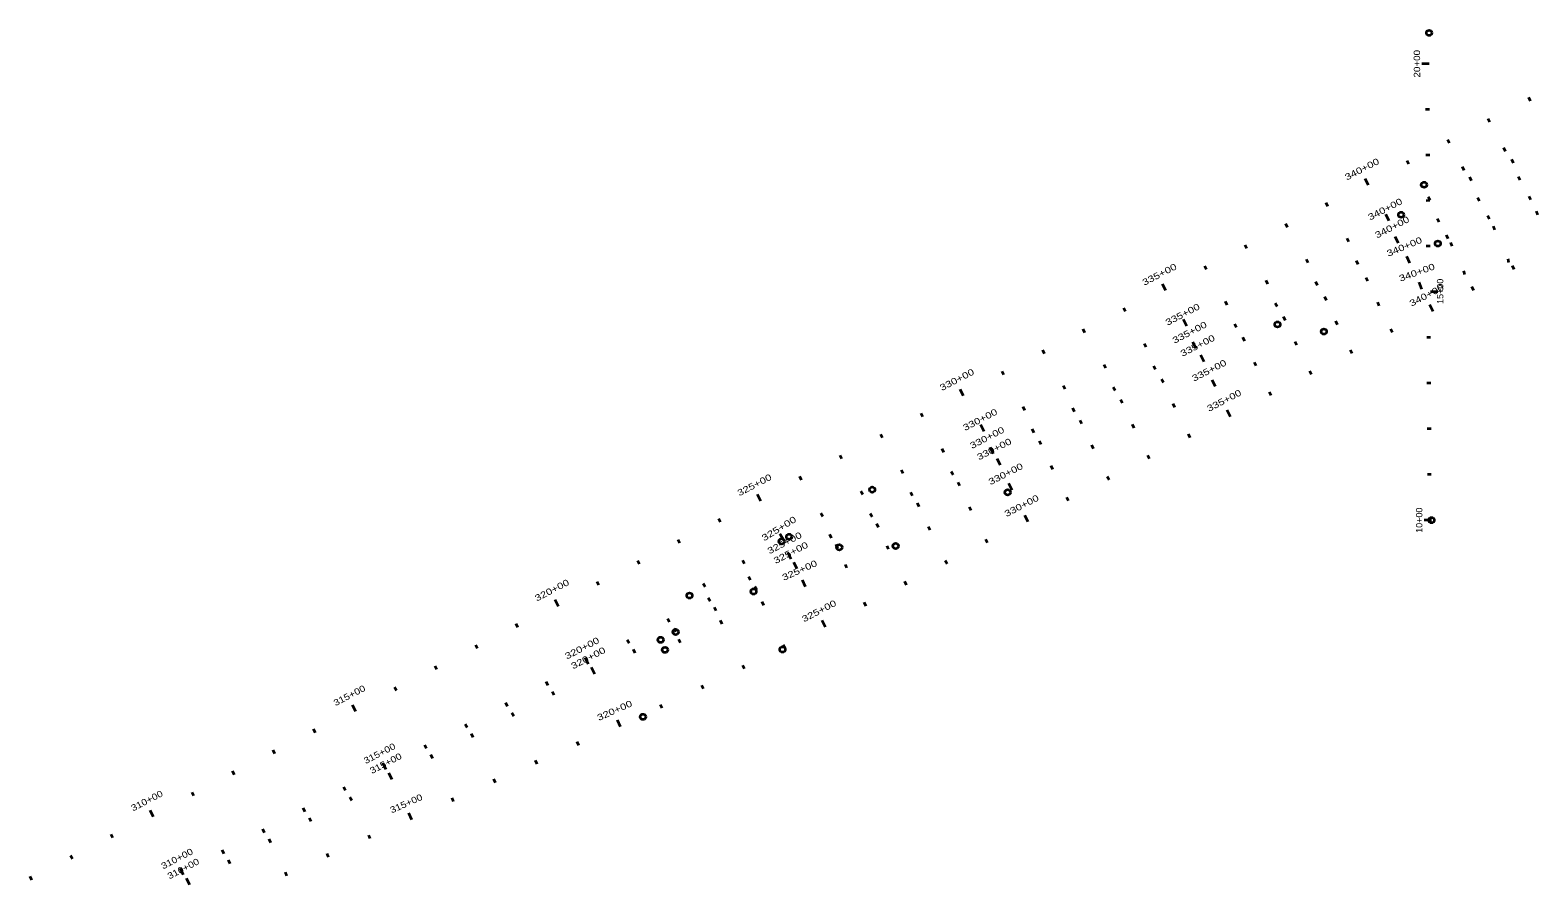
# Model space of a CAD drawing. Extents: x 2357892 to 2370172, y 6966790 to 6985499.
# Drawn here: x 2358624 to 2361928, y 6976232 to 6978104 of the extents above; entities that cross this region are included whole.
import ezdxf
from ezdxf.enums import TextEntityAlignment as Align

# ---------------------------------------------------------------- set-up
doc = ezdxf.new("R2010")
doc.units = 0
doc.header["$LTSCALE"] = 5.6
doc.layers.add('28', color=7, linetype='Continuous', lineweight=35)

msp = doc.modelspace()

# ---------------------------------------------------------------- linework, layer by layer
at = {"layer": '28'}
for p, q in [((2361689.654, 6978030.649), (2361673.654, 6978030.571)), ((2361911.419, 6977948.732), (2361907.499, 6977956.274)), ((2361690.143, 6977930.65), (2361681.643, 6977930.609)), ((2361822.689, 6977902.614), (2361818.769, 6977910.156)), ((2361733.958, 6977856.495), (2361730.038, 6977864.037)), ((2361645.228, 6977810.376), (2361641.308, 6977817.919)), ((2361690.632, 6977830.651), (2361682.132, 6977830.61)), ((2361852.631, 6977846.747), (2361856.096, 6977838.985)), ((2361873.898, 6977813.13), (2361870.708, 6977821.009)), ((2361761.677, 6977805.189), (2361765.276, 6977797.489)), ((2361888.729, 6977775.541), (2361884.809, 6977783.083)), ((2361556.498, 6977764.258), (2361549.119, 6977778.455)), ((2361781.88, 6977773.993), (2361778.418, 6977781.755)), ((2361467.767, 6977718.139), (2361463.847, 6977725.681)), ((2361691.121, 6977730.653), (2361682.622, 6977730.611)), ((2361691.285, 6977731.668), (2361687.553, 6977739.305)), ((2361799.996, 6977729.427), (2361796.076, 6977736.969)), ((2361912.073, 6977732.338), (2361908.457, 6977740.031)), ((2361602.153, 6977686.337), (2361594.775, 6977700.534)), ((2361711.263, 6977683.312), (2361707.344, 6977690.854)), ((2361821.568, 6977689.806), (2361817.953, 6977697.499)), ((2361927.536, 6977699.692), (2361924.809, 6977707.743)), ((2361379.037, 6977672.021), (2361375.117, 6977679.563)), ((2361622.531, 6977637.198), (2361615.153, 6977651.395)), ((2361731.064, 6977647.274), (2361727.449, 6977654.967)), ((2361833.201, 6977666.517), (2361830.288, 6977674.502)), ((2361290.306, 6977625.902), (2361286.386, 6977633.444)), ((2361513.421, 6977640.222), (2361509.501, 6977647.765)), ((2361691.61, 6977630.654), (2361683.111, 6977630.612)), ((2361739.664, 6977631.157), (2361736.566, 6977639.072)), ((2361201.576, 6977579.784), (2361197.656, 6977587.326)), ((2361424.688, 6977594.108), (2361420.768, 6977601.65)), ((2361533.798, 6977591.084), (2361529.879, 6977598.626)), ((2361646.974, 6977593.631), (2361640.798, 6977608.391)), ((2361864.288, 6977595.163), (2361862.239, 6977603.412)), ((2361875.682, 6977580.078), (2361871.763, 6977587.621)), ((2361335.955, 6977547.994), (2361332.036, 6977555.536)), ((2361445.066, 6977544.969), (2361441.146, 6977552.512)), ((2361555.182, 6977553.96), (2361551.72, 6977561.723)), ((2361673.062, 6977536.888), (2361667.603, 6977551.928)), ((2361767.912, 6977568.529), (2361765.434, 6977576.66)), ((2361112.846, 6977533.665), (2361105.467, 6977547.862)), ((2361464.338, 6977512.166), (2361460.695, 6977519.846)), ((2361708.1, 6977530.733), (2361692.1, 6977530.655)), ((2361786.942, 6977533.979), (2361783.023, 6977541.522)), ((2361024.115, 6977487.546), (2361020.195, 6977495.089)), ((2361247.223, 6977501.88), (2361243.303, 6977509.422)), ((2361356.333, 6977498.855), (2361352.413, 6977506.397)), ((2361579.998, 6977500.326), (2361576.684, 6977508.153)), ((2361698.201, 6977487.879), (2361690.825, 6977502.078)), ((2361158.49, 6977455.765), (2361151.112, 6977469.963)), ((2361267.6, 6977452.741), (2361263.681, 6977460.283)), ((2361374.489, 6977468.27), (2361370.67, 6977475.864)), ((2361488.975, 6977458.943), (2361485.255, 6977466.587)), ((2360935.385, 6977441.428), (2360931.465, 6977448.97)), ((2361178.868, 6977406.627), (2361171.49, 6977420.824)), ((2361285.339, 6977422.969), (2361281.485, 6977430.545)), ((2361399.709, 6977413.873), (2361395.855, 6977421.45)), ((2361609.461, 6977441.78), (2361605.543, 6977449.323)), ((2361692.589, 6977430.656), (2361684.089, 6977430.615)), ((2360846.655, 6977395.309), (2360842.735, 6977402.851)), ((2361069.758, 6977409.651), (2361065.838, 6977417.193)), ((2361196.209, 6977377.628), (2361188.954, 6977391.889)), ((2361520.721, 6977395.68), (2361516.802, 6977403.223)), ((2360757.924, 6977349.191), (2360754.004, 6977356.733)), ((2360981.025, 6977363.537), (2360977.105, 6977371.079)), ((2361090.135, 6977360.512), (2361086.216, 6977368.055)), ((2361310.576, 6977368.538), (2361306.722, 6977376.114)), ((2361431.98, 6977349.581), (2361428.062, 6977357.124)), ((2360892.292, 6977317.423), (2360888.373, 6977324.965)), ((2361001.403, 6977314.398), (2360997.483, 6977321.94)), ((2361107.078, 6977332.287), (2361103.224, 6977339.863)), ((2361221.443, 6977323.202), (2361214.189, 6977337.463)), ((2361693.078, 6977330.657), (2361684.578, 6977330.616)), ((2360669.194, 6977303.072), (2360661.815, 6977317.269)), ((2361017.948, 6977286.947), (2361014.094, 6977294.523)), ((2361343.24, 6977303.481), (2361339.322, 6977311.024)), ((2360580.464, 6977256.954), (2360576.543, 6977264.496)), ((2360803.56, 6977271.308), (2360799.64, 6977278.851)), ((2360912.67, 6977268.284), (2360908.75, 6977275.826)), ((2361132.31, 6977277.866), (2361128.456, 6977285.442)), ((2361254.5, 6977257.382), (2361247.124, 6977271.58)), ((2360714.827, 6977225.194), (2360707.449, 6977239.391)), ((2360823.938, 6977222.169), (2360820.018, 6977229.712)), ((2360928.818, 6977241.606), (2360924.964, 6977249.182)), ((2361043.177, 6977232.53), (2361039.324, 6977240.106)), ((2361693.567, 6977230.659), (2361685.067, 6977230.617)), ((2360491.733, 6977210.835), (2360487.813, 6977218.377)), ((2360735.205, 6977176.055), (2360727.827, 6977190.252)), ((2360839.687, 6977196.265), (2360835.833, 6977203.841)), ((2360954.044, 6977187.194), (2360950.191, 6977194.77)), ((2361165.76, 6977211.282), (2361161.841, 6977218.825)), ((2360403.003, 6977164.716), (2360399.083, 6977172.259)), ((2360626.095, 6977179.08), (2360622.175, 6977186.622)), ((2360750.557, 6977150.925), (2360743.302, 6977165.186)), ((2361077.019, 6977165.183), (2361073.101, 6977172.726)), ((2360314.272, 6977118.598), (2360310.352, 6977126.14)), ((2360537.362, 6977132.965), (2360533.442, 6977140.508)), ((2360646.472, 6977129.941), (2360642.553, 6977137.483)), ((2360864.912, 6977141.858), (2360861.058, 6977149.435)), ((2360988.279, 6977119.083), (2360984.361, 6977126.626)), ((2361694.056, 6977130.66), (2361685.556, 6977130.618)), ((2360448.673, 6977086.767), (2360444.692, 6977094.277)), ((2360557.74, 6977083.827), (2360553.82, 6977091.369)), ((2360661.426, 6977105.584), (2360657.573, 6977113.16)), ((2360775.779, 6977096.522), (2360768.525, 6977110.784)), ((2360225.542, 6977072.479), (2360218.163, 6977086.676)), ((2360572.296, 6977060.243), (2360568.442, 6977067.819)), ((2360686.335, 6977051.806), (2360682.6, 6977059.442)), ((2360899.539, 6977072.984), (2360895.62, 6977080.527)), ((2360136.812, 6977026.361), (2360132.892, 6977033.903)), ((2360361.154, 6977038.4), (2360356.914, 6977045.767)), ((2360469.007, 6977037.712), (2360465.087, 6977045.255)), ((2360810.799, 6977026.884), (2360803.423, 6977041.083)), ((2361694.545, 6977030.661), (2361678.545, 6977030.583)), ((2360275.358, 6976987.037), (2360266.963, 6977000.657)), ((2360380.275, 6976991.598), (2360376.355, 6976999.14)), ((2360483.166, 6977014.903), (2360479.312, 6977022.479)), ((2360596.129, 6977008.648), (2360592.527, 6977016.348)), ((2360048.081, 6976980.242), (2360044.161, 6976987.784)), ((2360291.542, 6976945.484), (2360284.164, 6976959.681)), ((2360394.035, 6976969.562), (2360390.18, 6976977.137)), ((2360505.193, 6976967.049), (2360501.704, 6976974.799)), ((2360722.058, 6976980.785), (2360718.14, 6976988.328)), ((2359959.351, 6976934.124), (2359955.431, 6976941.666)), ((2360189.823, 6976935.234), (2360185.484, 6976942.543)), ((2360305.012, 6976924.012), (2360297.693, 6976938.24)), ((2360414.009, 6976925.995), (2360410.519, 6976933.746)), ((2360633.318, 6976934.685), (2360629.4, 6976942.228)), ((2359870.621, 6976888.005), (2359866.701, 6976895.547)), ((2360103.398, 6976884.931), (2360099.187, 6976892.314)), ((2360202.809, 6976899.37), (2360198.89, 6976906.912)), ((2360322.824, 6976884.942), (2360316.256, 6976899.531)), ((2360544.578, 6976888.586), (2360540.659, 6976896.128)), ((2360114.077, 6976853.255), (2360110.157, 6976860.798)), ((2360216.188, 6976878.075), (2360212.266, 6976885.616)), ((2359781.89, 6976841.886), (2359774.511, 6976856.083)), ((2360127.479, 6976831.915), (2360123.555, 6976839.455)), ((2360231.64, 6976843.888), (2360228.15, 6976851.639)), ((2360455.838, 6976842.486), (2360451.919, 6976850.029)), ((2359693.16, 6976795.768), (2359689.24, 6976803.31)), ((2360025.344, 6976807.141), (2360021.424, 6976814.683)), ((2360038.771, 6976785.753), (2360034.847, 6976793.293)), ((2360140.455, 6976802.835), (2360136.966, 6976810.585)), ((2360367.097, 6976796.386), (2360359.721, 6976810.585)), ((2359936.612, 6976761.027), (2359932.692, 6976768.569)), ((2360049.271, 6976761.781), (2360045.781, 6976769.532)), ((2359604.43, 6976749.649), (2359600.509, 6976757.191)), ((2359847.879, 6976714.912), (2359840.501, 6976729.11)), ((2359950.063, 6976739.592), (2359946.139, 6976747.132)), ((2360278.357, 6976750.287), (2360274.439, 6976757.83)), ((2359515.699, 6976703.531), (2359511.779, 6976711.073)), ((2359861.355, 6976693.43), (2359853.969, 6976707.624)), ((2360189.268, 6976704.868), (2360185.473, 6976712.474)), ((2359426.969, 6976657.412), (2359423.049, 6976664.954)), ((2359759.146, 6976668.798), (2359755.227, 6976676.34)), ((2360099.401, 6976661.009), (2360095.74, 6976668.68)), ((2359670.414, 6976622.684), (2359666.494, 6976630.226)), ((2359772.647, 6976647.269), (2359768.723, 6976654.809)), ((2360008.782, 6976618.724), (2360005.255, 6976626.457)), ((2359338.238, 6976611.294), (2359330.859, 6976625.49)), ((2359683.938, 6976601.108), (2359680.015, 6976608.648)), ((2359249.508, 6976565.175), (2359245.588, 6976572.717)), ((2359581.681, 6976576.57), (2359577.761, 6976584.112)), ((2359595.23, 6976554.946), (2359591.307, 6976562.486)), ((2359917.543, 6976577.792), (2359911.021, 6976592.402)), ((2359492.949, 6976530.455), (2359489.029, 6976537.998)), ((2359826.23, 6976537.027), (2359822.765, 6976544.788)), ((2359160.778, 6976519.056), (2359156.858, 6976526.599)), ((2359404.216, 6976484.341), (2359396.838, 6976498.538)), ((2359506.522, 6976508.785), (2359502.599, 6976516.325)), ((2359734.916, 6976496.262), (2359731.451, 6976504.023)), ((2359072.047, 6976472.938), (2359068.127, 6976480.48)), ((2359417.814, 6976462.623), (2359410.428, 6976476.817)), ((2359643.602, 6976455.496), (2359640.137, 6976463.258)), ((2358983.317, 6976426.819), (2358979.397, 6976434.361)), ((2359315.483, 6976438.227), (2359311.564, 6976445.769)), ((2359226.751, 6976392.113), (2359222.831, 6976399.655)), ((2359329.106, 6976416.462), (2359325.182, 6976424.002)), ((2359552.288, 6976414.731), (2359548.823, 6976422.493)), ((2358894.587, 6976380.701), (2358887.208, 6976394.898)), ((2359240.398, 6976370.3), (2359236.474, 6976377.841)), ((2359460.975, 6976373.966), (2359454.452, 6976388.576)), ((2358805.856, 6976334.582), (2358801.936, 6976342.124)), ((2359138.018, 6976345.998), (2359134.098, 6976353.541)), ((2359151.69, 6976324.139), (2359147.766, 6976331.679)), ((2359369.661, 6976333.201), (2359366.196, 6976340.962)), ((2359049.286, 6976299.884), (2359045.366, 6976307.426)), ((2359278.347, 6976292.436), (2359274.882, 6976300.197)), ((2358717.126, 6976288.464), (2358713.206, 6976296.006)), ((2358960.553, 6976253.77), (2358953.175, 6976267.967)), ((2359062.982, 6976277.978), (2359059.058, 6976285.518)), ((2358628.396, 6976242.345), (2358624.475, 6976249.887)), ((2358974.274, 6976231.816), (2358966.888, 6976246.009)), ((2359187.033, 6976251.67), (2359183.568, 6976259.432))]:
    msp.add_line(p, q, dxfattribs=at)
for centre in [(2361689.324, 6978098.15), (2361678.267, 6977765.373), (2361627.907, 6977699.721), (2361708.438, 6977636.641), (2361357.195, 6977459.522), (2361458.8, 6977443.929), (2360469.308, 6977097.598), (2360766.093, 6977091.596), (2361694.545, 6977030.661), (2360270.906, 6976984.293), (2360287.175, 6976994.321), (2360397.357, 6976971.252), (2360520.732, 6976974.044), (2360069.012, 6976865.472), (2360209.253, 6976874.468), (2360038.771, 6976785.753), (2360005.754, 6976768.572), (2360015.332, 6976746.501), (2360272.718, 6976747.358), (2359967.083, 6976599.908)]:
    msp.add_circle(centre, 6, dxfattribs=at)

# ---------------------------------------------------------------- texts
for s, rotation, width, p in [('20+00', 90.28, 1.15, (2361669.654, 6978030.587)), ('340+00', 27.464, 1.3, (2361545.43, 6977793.442)), ('340+00', 27.461, 1.3, (2361596.158, 6977705.761)), ('340+00', 27.461, 1.3, (2361611.464, 6977666.383)), ('340+00', 22.707, 1.3, (2361637.71, 6977623.36)), ('335+00', 27.464, 1.3, (2361101.777, 6977562.849)), ('340+00', 19.948, 1.3, (2361664.873, 6977566.894)), ('15+00', 90.28, 1.05, (2361720.516, 6977532.095)), ('340+00', 27.451, 1.3, (2361687.138, 6977517.065)), ('335+00', 27.461, 1.3, (2361152.495, 6977475.189)), ('335+00', 27.461, 1.3, (2361167.801, 6977435.811)), ('335+00', 26.962, 1.3, (2361185.327, 6977406.873)), ('330+00', 27.464, 1.3, (2360658.126, 6977332.257)), ('335+00', 26.959, 1.3, (2361210.563, 6977352.448)), ('335+00', 27.451, 1.3, (2361243.436, 6977286.567)), ('330+00', 27.461, 1.3, (2360708.833, 6977244.618)), ('330+00', 27.461, 1.3, (2360724.138, 6977205.24)), ('330+00', 26.962, 1.3, (2360739.676, 6977180.17)), ('330+00', 26.959, 1.3, (2360764.898, 6977125.768)), ('325+00', 27.464, 1.3, (2360214.473, 6977101.664)), ('330+00', 27.451, 1.3, (2360799.736, 6977056.071)), ('10+00', 90.28, 1.05, (2361674.545, 6977030.599)), ('325+00', 31.649, 1.35, (2360268.537, 6977006.327)), ('325+00', 27.461, 1.3, (2360280.475, 6976974.668)), ('325+00', 27.222, 1.3, (2360294.033, 6976953.226)), ('325+00', 24.238, 1.3, (2360312.972, 6976914.503)), ('320+00', 27.464, 1.3, (2359770.822, 6976871.071)), ('325+00', 27.451, 1.3, (2360356.034, 6976825.572)), ('320+00', 27.461, 1.3, (2359836.812, 6976744.097)), ('320+00', 27.491, 1.3, (2359850.277, 6976722.612)), ('315+00', 27.464, 1.2, (2359327.17, 6976640.478)), ('320+00', 24.057, 1.3, (2359907.761, 6976607.374)), ('315+00', 27.461, 1.2, (2359393.149, 6976513.526)), ('315+00', 27.491, 1.2, (2359406.735, 6976491.804)), ('310+00', 27.464, 1.2, (2358883.519, 6976409.885)), ('315+00', 24.057, 1.2, (2359451.191, 6976403.548)), ('310+00', 27.461, 1.2, (2358949.487, 6976282.954)), ('310+00', 27.491, 1.2, (2358963.196, 6976260.998))]:
    msp.add_text(s, height=14, rotation=rotation, dxfattribs=dict(at, width=width)).set_placement(p, align=Align.CENTER)

doc.saveas('drawing.dxf')
